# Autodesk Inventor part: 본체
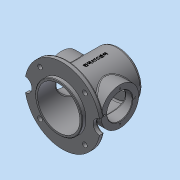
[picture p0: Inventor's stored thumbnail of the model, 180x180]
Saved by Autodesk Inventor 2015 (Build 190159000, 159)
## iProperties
Created: 2018-04
Part Number: 본체
Material: 일반
Document SubType Name: Modeling
Designer: Administrator
Density: 1 g/cm^3
Appearance: 기본값
Author: Administrator
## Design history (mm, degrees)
sketch "스케치1"
  geometry: 1 further point
sketch "스케치2"
  geometry: L1 (0, -64)-(0, 64); L2 (0, 64)-(-50, 64); L3 (-50, 64)-(-50, -64); L4 (-50, -64)-(0, -64); 2 further points
  constraints: 8 end point, 3 perpendicular, 1 coincident, 1 midpoint, 1 vertical
  dimensions: "d0" = 50 distance of L3.end L1.start; "d1" = 128 distance of L2.end L3.end
revolve "회전1" sketch "스케치2" stored, may be unused: angle "d2" = 90 deg
node "작업 평면1"
sketch "스케치3"
  geometry: C1 r 80 at (0, 0); 1 further point
  constraints: 1 centre point, 1 coincident
  dimensions: "d4" = 160 diameter of C1
extrude "돌출1" join sketch "스케치3" distance "d5" = 10; taper "d6" = 0 deg
sketch "스케치4"
  geometry: A1 r 80 centre (0, 0) between (-80, 0) and (80, 0) reference
  constraints: 2 horizontal alignment, 2 point on circle
hole "구멍1" sketch "스케치4" at (80, 0), (-80, 0) diameter "d7" = 30; stored, may be unused: countersink angle "d11" = 90 deg, drill point angle "d13" = 118 deg; dims "d8" = 6, "d9" = 4, "d10" = 2, "d12" = 8
sketch "스케치5" dims "d14" = 135
  geometry: L1 (0, 0)-(0, 102.247); L2 (0, 0)-(-71.221, 71.221); A1 r 80 centre (0, 0) between (-78.594, -14.934) and (78.594, -14.934) reference; 1 further point
  constraints: 4 end point, 1 coincident, 1 point on line, 1 vertical, 3 other
  dimensions: "d15" = 45 deg angle of L2 L1
hole "구멍2" sketch "스케치5" at (-47.73, 47.73) diameter "d16" = 10; stored, may be unused: countersink angle "d20" = 90 deg, drill point angle "d22" = 118 deg; dims "d17" = 6, "d18" = 4, "d19" = 2, "d21" = 8
fillet "모깎기1" dims "d26" = 3
sketch "스케치6"
  geometry: C1 r 50 at (0, 0) reference; C2 r 40 at (0, 0)
  constraints: 1 centre point, 1 coincident
  dimensions: "d27" = 80 diameter of C2
extrude "돌출2" join sketch "스케치6" distance "d28" = 5; taper "d29" = 0 deg
fillet "모깎기2" dims "d30" = 3
sketch "스케치7"
  geometry: L1 (0, -64)-(0, 69); L2 (0, 69)-(-27, 69); L3 (-27, 69)-(-27, 56); L4 (-27, 56)-(-45, 56); L5 (-45, 56)-(-45, -64); L6 (-45, -64)-(0, -64); L7 (40, 69)-(-40, 69) reference; 1 further point
  constraints: 12 end point, 5 perpendicular, 1 midpoint, 1 point on line, 1 vertical
  dimensions: "d31" = 133 distance of L1.start L1.end; "d32" = 45 distance of L5.end L1.start; "d33" = 27 distance of L1.end L2.end; "d34" = 120 distance of L4.end L5.end
revolve "회전2" sketch "스케치7" stored, may be unused: angle "d35" = 90 deg
chamfer "모따기1" distance "d36" = 1; stored, may be unused: second distance "d37" = 2, angle "d38" = 45 deg
node "작업 평면2"
sketch "스케치8"
  geometry: L1 (-56, 14.934)-(-56, 80) reference; C1 r 40 at (4, 0); 1 further point
  constraints: 1 centre point, 1 horizontal alignment
  dimensions: "d40" = 60 distance from line of C1.centre L1; "d41" = 80 diameter of C1
extrude "돌출3" join sketch "스케치8" stored distance "d42" = 124; taper "d43" = 0 deg
sketch "스케치9"
  geometry: C1 r 40 at (0, 0) reference; C2 r 27 at (0, 0); 1 further point
  constraints: 1 centre point, 1 coincident
  dimensions: "d44" = 54 diameter of C2
extrude "돌출4" cut sketch "스케치9" distance "d45" = 124; taper "d46" = 0 deg
fillet "모깎기3" dims "d47" = 3
chamfer "모따기2" distance "d48" = 1; stored, may be unused: second distance "d49" = 2, angle "d50" = 45 deg
sketch "스케치10" dims "d51" = 65
  geometry: C1 r 40 at (0, 0) reference; C2 r 28 at (0, 0) reference; 2 further points
  constraints: 2 vertical alignment, 1 coincident, 2 other
hole "구멍3" sketch "스케치10" at (0, -32.5) diameter "d52" = 3.242; stored, may be unused: countersink angle "d56" = 90 deg, drill point angle "d58" = 118 deg; dims "d53" = 8, "d54" = 4, "d55" = 2, "d57" = 10
sketch "스케치11" dims "d62" = 65
  geometry: C1 r 40 at (0, 0) reference; C2 r 28 at (0, 0) reference; 3 further points
  constraints: 2 vertical alignment, 1 coincident, 2 other
hole "구멍4" sketch "스케치11" at (0, 32.5) diameter "d63" = 3.242; stored, may be unused: countersink angle "d67" = 90 deg, drill point angle "d69" = 118 deg; dims "d64" = 8, "d65" = 4, "d66" = 2, "d68" = 10
node "작업 평면3"
sketch "스케치12"
  geometry: L1 (78.594, -56)-(-78.594, -56) reference; 2 further points
  constraints: 1 vertical alignment, 1 other
  dimensions: "d74" = 70 distance from line of L1 point (0, 14)
feature "엠보싱1" sketch "스케치12" dims "d0" = 50, "d1" = 128, "d75" = 0.5, "d76" = 0
fillet "모깎기4" dims "d77" = 3
fillet "모깎기5" dims "d78" = 3
fillet "모깎기6" dims "d79" = 5
node "솔리드1"
pattern_circular "원형 패턴1" dims angle "d24" = 360 deg
mirror "대칭1"
pattern_circular "원형 패턴2" dims angle "d60" = 360 deg
pattern_circular "원형 패턴3" dims angle "d71" = 360 deg
mirror "대칭2"
other parameters: "d3" = -8, "d39" = 62, "d73" = 136.25
